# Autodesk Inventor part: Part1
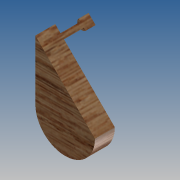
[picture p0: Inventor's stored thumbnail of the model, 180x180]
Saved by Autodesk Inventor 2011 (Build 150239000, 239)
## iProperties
Created: 2011-01
Part Number: Part1
Document SubType Name: Modeling
Designer: Microsoft
Density: 1 g/cm^3
Author: Microsoft
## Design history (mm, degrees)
sketch "Sketch1"
  geometry: L1 (9.525, 0)-(9.525, 19.05); L2 (-9.525, 19.05)-(-9.525, 0); L3 (-9.525, 19.05)-(9.525, 0); A1 r 9.525 centre (0, 0) between (-9.525, 0) and (9.525, 0); A2 r 9.525 centre (0, 19.05) between (9.525, 19.05) and (-9.525, 19.05); 1 further point
  constraints: 6 end point, 4 point on circle, 3 tangent, 2 centre point, 1 coincident, 1 vertical alignment
  dimensions: "d3" = 9.525 radius of A2; "d4" = 9.525 radius of A1; "d5" = 19.05 distance of L1.start L1.end; "d6" = 19.05 distance of point (0, 0) A2.centre
extrude "Extrusion1" new body sketch "Sketch1" distance "d7" = 19.05; taper "d8" = 0 deg
sketch "Sketch2"
  geometry: L1 (13.47, 0)-(13.47, 19.05) reference; C1 r 0.794 at (13.47, 9.525); 1 further point
  constraints: 1 centre point, 1 midpoint
  dimensions: "d9" = 1.5875 diameter of C1
extrude "Extrusion2" join sketch "Sketch2" distance "d10" = 6.35; taper "d11" = 0 deg
sketch "Sketch3"
  geometry: C1 r 0.794 at (0, 0) reference; C2 r 1.587 at (0, 0); 1 further point
  constraints: 1 centre point, 1 coincident
  dimensions: "d12" = 3.175 diameter of C2
extrude "Extrusion3" join sketch "Sketch3" distance "d13" = 0.79375; taper "d14" = 0 deg
workplane "Work Plane1"
sketch "Sketch5"
  geometry: L1 (-9.525, 19.05)-(-8.622, 19.953); L2 (9.525, 0)-(-9.525, 19.05) reference; C1 r 0.794 at (-7.28, 16.805); 1 further point
  constraints: 2 end point, 1 centre point, 1 perpendicular, 1 point on line
  dimensions: "d21" = 1.5875 diameter of C1; "d22" = 3.175 distance from line of L1 C1.centre
extrude "Extrusion4" cut sketch "Sketch5" distance "d23" = 6.35; taper "d24" = 0 deg
sketch "Sketch6"
  geometry: C1 r 1.588 at (-7.28, 16.805); A1 r 0.794 centre (-7.28, 16.805) between (-7.841, 17.366) and (-6.719, 16.244) reference; 1 further point
  constraints: 1 centre point, 1 coincident
  dimensions: "d25" = 3.175 diameter of C1
extrude "Extrusion5" cut sketch "Sketch6" distance "d26" = 3.175; taper "d27" = 0 deg
sketch "Sketch7"
  geometry: L1 (-9.525, 19.05)-(9.525, 0) reference; L2 (-9.525, 0)-(-9.525, 19.05) reference; A1 r 9.525 centre (0, 0) between (-9.525, 0) and (9.525, 0) reference
extrude "Extrusion6" sketch "Sketch7" distance "d28" = 6.35; taper "d29" = 0 deg
sketch "Sketch8"
  geometry: L1 (9.525, 19.05)-(-9.525, 0) reference; L2 (9.525, 19.05)-(5.951, 22.624); L3 (9.525, 19.05)-(-9.525, 0) reference; L4 (7.841, 17.366)-(6.719, 16.244); A1 r 0.794 centre (7.28, 16.805) between (6.719, 16.244) and (7.841, 17.366)
  constraints: 4 end point, 3 point on line, 2 point on circle, 1 centre point, 1 collinear, 1 perpendicular
  dimensions: "d30" = 1.5875 diameter of A1; "d31" = 3.175 distance from line of L2 A1.centre
extrude "Extrusion7" join sketch "Sketch8" distance "d32" = 6.35; taper "d33" = 0 deg
sketch "Sketch9"
  geometry: L1 (6.719, 16.244)-(7.841, 17.366) reference; L2 (9.525, 19.05)-(-9.525, 0) reference; L3 (6.157, 15.682)-(8.402, 17.927); A1 r 0.794 centre (7.28, 16.805) between (6.719, 16.244) and (7.841, 17.366) reference; A2 r 1.587 centre (7.28, 16.805) between (6.157, 15.682) and (8.402, 17.927); 1 further point
  constraints: 2 end point, 2 point on circle, 2 point on line, 1 centre point, 1 coincident
  dimensions: "d34" = 3.175 diameter of A2
extrude "Extrusion8" join sketch "Sketch9" distance "d35" = 3.175; taper "d36" = 0 deg
body "Solid1"
other parameters: "d17" = -6.35
